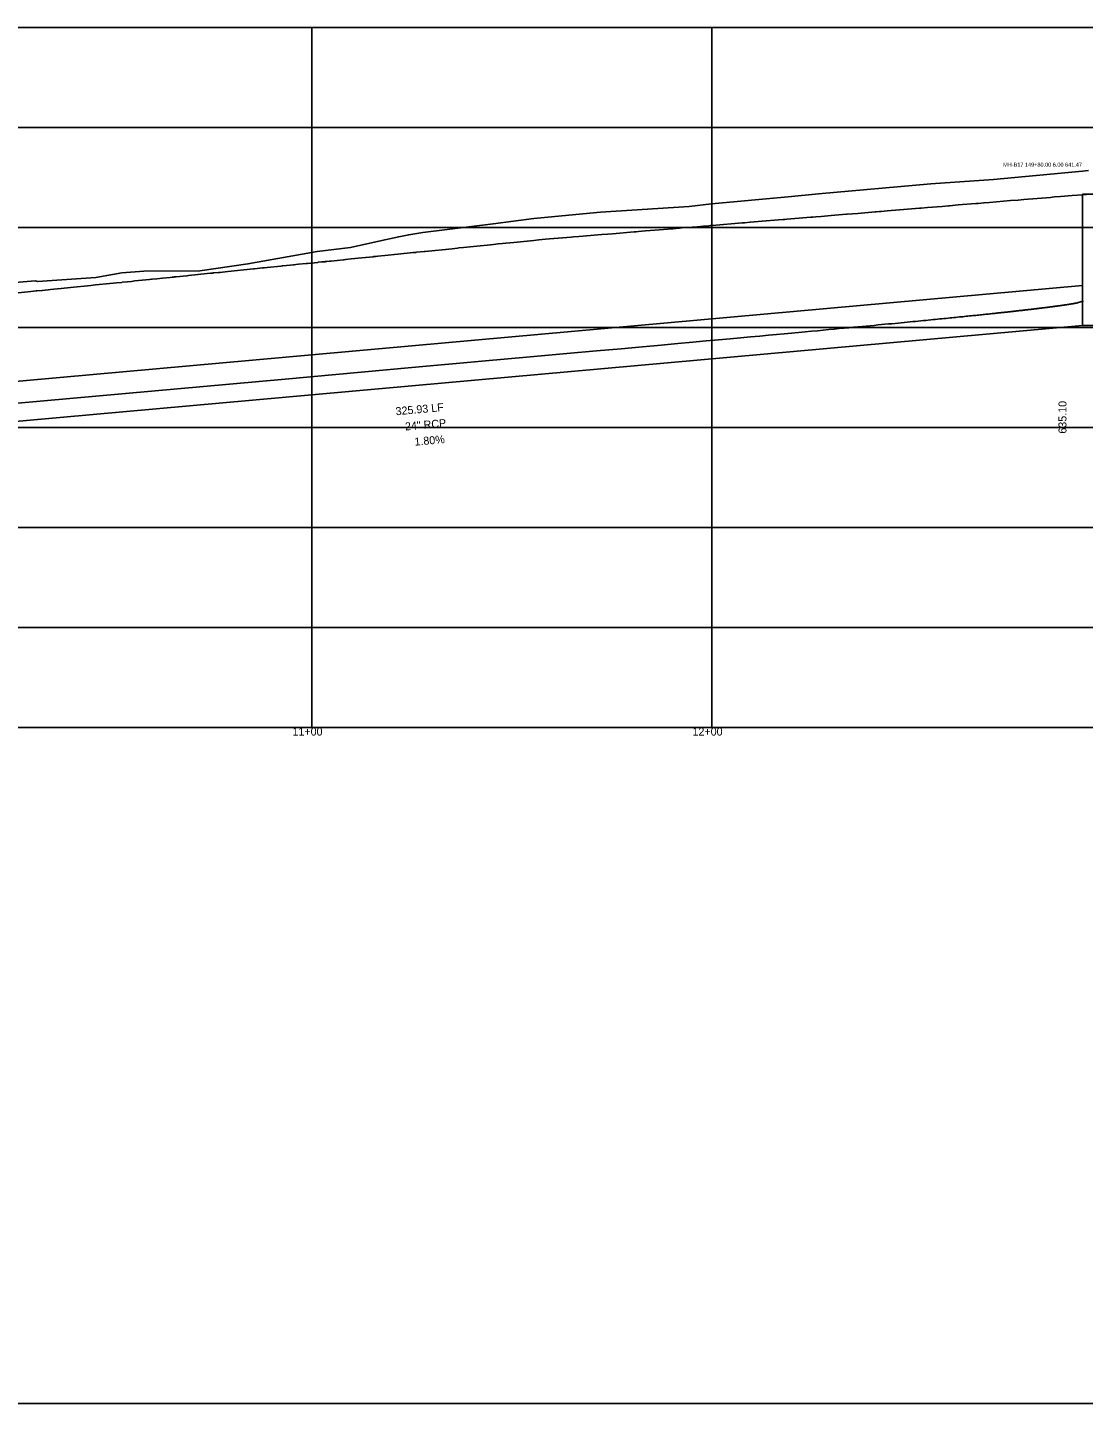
# Model space of a CAD drawing. Extents: x 2253035 to 2279930, y 13774972 to 13793443.
# Drawn here: x 2260990.4 to 2261254.4, y 13791972.5 to 13792316.4 of the extents above; entities that cross this region are included whole.
import ezdxf

# ---------------------------------------------------------------- set-up
doc = ezdxf.new("R2010")
doc.units = 0
for name, color, linetype in [('Default', 7, 'Continuous'), ('E_Utility_ATT_HH', 7, 'Continuous'), ('E_Utility_ATT_PR_PVC', 7, 'Continuous'), ('E_Utility_Telephone_Telephone Pedestal_TPED_Description', 7, 'Continuous'), ('E_Utillity_Water_Water Line_12in', 7, 'Continuous'), ('E_Utillity_Water_Water Line_1in', 7, 'Continuous'), ('E_Utillity_Water_Water Line_4in', 7, 'Continuous'), ('E_Utillity_Water_Water Line_8in', 7, 'Continuous')]:
    doc.layers.add(name, color=color, linetype=linetype)

msp = doc.modelspace()

# ---------------------------------------------------------------- linework, layer by layer
at = {"layer": 'Default'}
for p, q in [((2261061.48, 13792141.44), (2261061.48, 13792316.44)), ((2261161.48, 13792141.44), (2261161.48, 13792316.44)), ((2259961.48, 13792291.44), (2261350.66, 13792291.44)), ((2259961.48, 13792266.44), (2261350.66, 13792266.44)), ((2259961.48, 13792241.44), (2261350.66, 13792241.44)), ((2259961.48, 13792216.44), (2261350.66, 13792216.44)), ((2259961.48, 13792191.44), (2261350.66, 13792191.44)), ((2259961.48, 13792166.44), (2261350.66, 13792166.44)), ((2258357.4, 13791972.48), (2265626.63, 13791972.48))]:
    msp.add_line(p, q, dxfattribs=at)
msp.add_lwpolyline([(2259961.48, 13792141.44), (2259961.48, 13792316.44), (2261350.66, 13792316.44), (2261350.66, 13792141.44)], close=True, dxfattribs=at)
at = {"layer": 'E_Utility_ATT_PR_PVC'}
msp.add_lwpolyline([(2260926.73, 13792217.03), (2261054.83, 13792228.56), (2261086.54, 13792231.42), (2261104.03, 13792233), (2261116.08, 13792234.09), (2261125.26, 13792234.92), (2261132.66, 13792235.59), (2261138.86, 13792236.15), (2261144.18, 13792236.64), (2261148.84, 13792237.06), (2261152.99, 13792237.44), (2261156.72, 13792237.78), (2261160.11, 13792238.09), (2261163.21, 13792238.37), (2261166.06, 13792238.64), (2261168.71, 13792238.88), (2261171.17, 13792239.11), (2261173.48, 13792239.32), (2261175.65, 13792239.52), (2261177.69, 13792239.71), (2261179.62, 13792239.89), (2261181.44, 13792240.06), (2261183.18, 13792240.22), (2261184.83, 13792240.37), (2261186.41, 13792240.52), (2261187.91, 13792240.66), (2261189.35, 13792240.79), (2261190.73, 13792240.92), (2261192.06, 13792241.05), (2261193.34, 13792241.17), (2261194.56, 13792241.28), (2261195.75, 13792241.39), (2261196.89, 13792241.5), (2261197.99, 13792241.6), (2261199.06, 13792241.71), (2261200.09, 13792241.8), (2261201.09, 13792241.9), (2261202.05, 13792241.99), (2261202.99, 13792242.08), (2261203.9, 13792242.17), (2261204.79, 13792242.25), (2261205.65, 13792242.33), (2261206.49, 13792242.41), (2261207.3, 13792242.49), (2261208.09, 13792242.57), (2261208.86, 13792242.64), (2261209.61, 13792242.72), (2261210.35, 13792242.79), (2261211.06, 13792242.86), (2261211.76, 13792242.92), (2261212.44, 13792242.99), (2261213.11, 13792243.05), (2261213.76, 13792243.12), (2261214.39, 13792243.18), (2261215.01, 13792243.24), (2261215.62, 13792243.3), (2261216.22, 13792243.36), (2261216.8, 13792243.42), (2261217.37, 13792243.47), (2261217.92, 13792243.53), (2261218.47, 13792243.58), (2261219.01, 13792243.64), (2261219.53, 13792243.69), (2261220.05, 13792243.74), (2261220.55, 13792243.79), (2261221.05, 13792243.84), (2261221.53, 13792243.89), (2261222.01, 13792243.94), (2261222.48, 13792243.98), (2261222.94, 13792244.03), (2261223.39, 13792244.08), (2261223.83, 13792244.12), (2261224.26, 13792244.16), (2261224.69, 13792244.21), (2261225.11, 13792244.25), (2261225.53, 13792244.29), (2261225.93, 13792244.33), (2261226.33, 13792244.37), (2261226.72, 13792244.42), (2261227.11, 13792244.45), (2261227.49, 13792244.49), (2261227.86, 13792244.53), (2261228.23, 13792244.57), (2261228.59, 13792244.61), (2261228.95, 13792244.65), (2261229.3, 13792244.68), (2261229.64, 13792244.72), (2261229.98, 13792244.75), (2261230.32, 13792244.79), (2261230.64, 13792244.82), (2261230.97, 13792244.86), (2261231.29, 13792244.89), (2261231.6, 13792244.92), (2261231.91, 13792244.96), (2261232.22, 13792244.99), (2261232.52, 13792245.02), (2261232.82, 13792245.05), (2261233.11, 13792245.09), (2261233.4, 13792245.12), (2261233.68, 13792245.15), (2261233.96, 13792245.18), (2261234.24, 13792245.21), (2261234.51, 13792245.24), (2261234.78, 13792245.27), (2261235.05, 13792245.29), (2261235.31, 13792245.32), (2261235.57, 13792245.35), (2261235.82, 13792245.38), (2261236.07, 13792245.41), (2261236.32, 13792245.43), (2261236.56, 13792245.46), (2261236.8, 13792245.49), (2261237.04, 13792245.51), (2261237.28, 13792245.54), (2261237.51, 13792245.57), (2261237.74, 13792245.59), (2261237.96, 13792245.62), (2261238.19, 13792245.64), (2261238.41, 13792245.67), (2261238.62, 13792245.69), (2261238.84, 13792245.72), (2261239.05, 13792245.74), (2261239.26, 13792245.76), (2261239.47, 13792245.79), (2261239.67, 13792245.81), (2261239.87, 13792245.83), (2261240.07, 13792245.86), (2261240.27, 13792245.88), (2261240.46, 13792245.9), (2261240.66, 13792245.92), (2261240.84, 13792245.95), (2261241.03, 13792245.97), (2261241.22, 13792245.99), (2261241.4, 13792246.01), (2261241.58, 13792246.03), (2261241.76, 13792246.05), (2261241.94, 13792246.07), (2261242.11, 13792246.1), (2261242.28, 13792246.12), (2261242.45, 13792246.14), (2261242.62, 13792246.16), (2261242.79, 13792246.18), (2261242.95, 13792246.2), (2261243.11, 13792246.22), (2261243.27, 13792246.23), (2261243.43, 13792246.25), (2261243.59, 13792246.27), (2261243.74, 13792246.29), (2261243.9, 13792246.31), (2261244.05, 13792246.33), (2261244.2, 13792246.35), (2261244.35, 13792246.37), (2261244.49, 13792246.38), (2261244.64, 13792246.4), (2261244.78, 13792246.42), (2261244.92, 13792246.44), (2261245.06, 13792246.46), (2261245.2, 13792246.47), (2261245.33, 13792246.49), (2261245.47, 13792246.51), (2261245.6, 13792246.52), (2261245.73, 13792246.54), (2261245.87, 13792246.56), (2261245.99, 13792246.57), (2261246.12, 13792246.59), (2261246.25, 13792246.61), (2261246.37, 13792246.62), (2261246.5, 13792246.64), (2261246.62, 13792246.66), (2261246.74, 13792246.67), (2261246.86, 13792246.69), (2261246.98, 13792246.7), (2261247.09, 13792246.72), (2261247.21, 13792246.73), (2261247.32, 13792246.75), (2261247.44, 13792246.76), (2261247.55, 13792246.78), (2261247.66, 13792246.79), (2261247.77, 13792246.81), (2261247.87, 13792246.82), (2261247.98, 13792246.84), (2261248.09, 13792246.85), (2261248.19, 13792246.87), (2261248.29, 13792246.88), (2261248.4, 13792246.9), (2261248.5, 13792246.91), (2261248.6, 13792246.92), (2261248.7, 13792246.94), (2261248.79, 13792246.95), (2261248.89, 13792246.97), (2261248.99, 13792246.98), (2261249.08, 13792246.99), (2261249.17, 13792247.01), (2261249.27, 13792247.02), (2261249.36, 13792247.03), (2261249.45, 13792247.05), (2261249.54, 13792247.06), (2261249.63, 13792247.07), (2261249.71, 13792247.08), (2261249.8, 13792247.1), (2261249.89, 13792247.11), (2261249.97, 13792247.12), (2261250.05, 13792247.14), (2261250.14, 13792247.15), (2261250.22, 13792247.16), (2261250.3, 13792247.17), (2261250.38, 13792247.18), (2261250.46, 13792247.2), (2261250.54, 13792247.21), (2261250.62, 13792247.22), (2261250.69, 13792247.23), (2261250.77, 13792247.24), (2261250.84, 13792247.26), (2261250.92, 13792247.27), (2261250.99, 13792247.28), (2261251.06, 13792247.29), (2261251.13, 13792247.3), (2261251.2, 13792247.31), (2261251.27, 13792247.32), (2261251.34, 13792247.34), (2261251.41, 13792247.35), (2261251.48, 13792247.36), (2261251.55, 13792247.37), (2261251.61, 13792247.38), (2261251.68, 13792247.39), (2261251.74, 13792247.4), (2261251.81, 13792247.41), (2261251.87, 13792247.42), (2261251.93, 13792247.43), (2261251.99, 13792247.44), (2261252.05, 13792247.46), (2261252.11, 13792247.47), (2261252.17, 13792247.48), (2261252.23, 13792247.49), (2261252.29, 13792247.5), (2261252.35, 13792247.51), (2261252.41, 13792247.52), (2261252.46, 13792247.53), (2261252.52, 13792247.54), (2261252.57, 13792247.55), (2261252.63, 13792247.56), (2261252.68, 13792247.57), (2261252.73, 13792247.58), (2261252.78, 13792247.6), (2261252.84, 13792247.61), (2261252.89, 13792247.63), (2261252.94, 13792247.64), (2261252.99, 13792247.65), (2261253.04, 13792247.67), (2261253.09, 13792247.68), (2261253.13, 13792247.69), (2261253.18, 13792247.71), (2261253.23, 13792247.72), (2261253.27, 13792247.73), (2261253.32, 13792247.75), (2261253.36, 13792247.76), (2261253.41, 13792247.77), (2261253.45, 13792247.79), (2261253.5, 13792247.8), (2261253.54, 13792247.81), (2261253.58, 13792247.83), (2261253.62, 13792247.84), (2261253.66, 13792247.85), (2261253.71, 13792247.86), (2261253.75, 13792247.87), (2261253.79, 13792247.89), (2261253.82, 13792247.9), (2261253.86, 13792247.91), (2261253.9, 13792247.92), (2261253.94, 13792247.93), (2261253.98, 13792247.95), (2261254.01, 13792247.96), (2261254.05, 13792247.97), (2261254.08, 13792247.98), (2261254.12, 13792247.99), (2261254.15, 13792248), (2261254.19, 13792248.01), (2261254.22, 13792248.03), (2261254.25, 13792248.04), (2261254.29, 13792248.05), (2261254.32, 13792248.06), (2261254.35, 13792248.07), (2261254.38, 13792248.08), (2261254.41, 13792248.09), (2261254.44, 13792248.1)], dxfattribs=at)
at = {"layer": 'E_Utillity_Water_Water Line_12in'}
msp.add_lwpolyline([(2261254.16, 13792274.78), (2261257.16, 13792274.78), (2261257.16, 13792241.94), (2261254.16, 13792241.94)], close=True, dxfattribs=at)
at = {"layer": 'E_Utillity_Water_Water Line_1in'}
msp.add_lwpolyline([(2260987.35, 13792252.7), (2260992.38, 13792253.09), (2260992.96, 13792252.94), (2261007.51, 13792253.92), (2261014.05, 13792255.16), (2261019.51, 13792255.52), (2261033.51, 13792255.61), (2261045.54, 13792257.33), (2261062.82, 13792260.44), (2261071.18, 13792261.43), (2261079.76, 13792263.38), (2261083.24, 13792264.12), (2261085.76, 13792264.64), (2261089.25, 13792265.17), (2261106.87, 13792267.4), (2261117.02, 13792268.7), (2261133.7, 13792270.32), (2261155.85, 13792271.7), (2261161.43, 13792272.38), (2261180.58, 13792274.08), (2261188.14, 13792274.9), (2261216.28, 13792277.35), (2261231.93, 13792278.48), (2261254.16, 13792280.53), (2261254.16, 13792280.53), (2261255.66, 13792280.67)], dxfattribs=at)
at = {"layer": 'E_Utillity_Water_Water Line_4in'}
for p, q in [((2260928.23, 13792222.61), (2261254.16, 13792251.94)), ((2260928.23, 13792212.61), (2261254.16, 13792241.94))]:
    msp.add_line(p, q, dxfattribs=at)
at = {"layer": 'E_Utillity_Water_Water Line_8in'}
msp.add_lwpolyline([(2260988.13, 13792250.12), (2260991.31, 13792250.44), (2260992.63, 13792250.59), (2260992.69, 13792250.59), (2260992.74, 13792250.59), (2260994.12, 13792250.73), (2260995.64, 13792250.88), (2260996.16, 13792250.93), (2260997.06, 13792251.03), (2260998.86, 13792251.21), (2261001.17, 13792251.44), (2261006.29, 13792251.96), (2261007.46, 13792252.08), (2261011.04, 13792252.44), (2261012.68, 13792252.61), (2261012.69, 13792252.61), (2261012.71, 13792252.61), (2261014, 13792252.74), (2261014.08, 13792252.75), (2261015.47, 13792252.89), (2261016.43, 13792252.99), (2261017.3, 13792253.08), (2261020.9, 13792253.44), (2261021.43, 13792253.5), (2261021.43, 13792253.5), (2261021.55, 13792253.51), (2261021.56, 13792253.51), (2261021.59, 13792253.51), (2261021.59, 13792253.51), (2261021.62, 13792253.52), (2261022.78, 13792253.63), (2261024.16, 13792253.77), (2261026.12, 13792253.97), (2261026.57, 13792254.02), (2261026.92, 13792254.06), (2261027.17, 13792254.08), (2261027.55, 13792254.12), (2261027.58, 13792254.12), (2261027.6, 13792254.13), (2261027.6, 13792254.13), (2261030.27, 13792254.4), (2261030.35, 13792254.41), (2261030.38, 13792254.41), (2261030.39, 13792254.41), (2261030.39, 13792254.41), (2261030.7, 13792254.44), (2261035.36, 13792254.92), (2261036.15, 13792255), (2261036.74, 13792255.06), (2261036.97, 13792255.08), (2261038.22, 13792255.21), (2261038.56, 13792255.24), (2261039.2, 13792255.31), (2261040.51, 13792255.44), (2261046.93, 13792256.1), (2261047.21, 13792256.13), (2261049.21, 13792256.33), (2261049.56, 13792256.37), (2261050.32, 13792256.44), (2261053.75, 13792256.79), (2261054.13, 13792256.83), (2261054.27, 13792256.85), (2261056.11, 13792257.03), (2261056.9, 13792257.11), (2261057.06, 13792257.13), (2261057.13, 13792257.14), (2261057.53, 13792257.18), (2261058.22, 13792257.25), (2261060.14, 13792257.44), (2261060.36, 13792257.49), (2261060.37, 13792257.49), (2261060.37, 13792257.47), (2261060.39, 13792257.47), (2261060.39, 13792257.47), (2261060.39, 13792257.47), (2261060.4, 13792257.47), (2261060.4, 13792257.47), (2261063.03, 13792257.74), (2261063.13, 13792257.75), (2261064.04, 13792257.84), (2261064.75, 13792257.91), (2261064.93, 13792257.93), (2261065.11, 13792257.95), (2261065.21, 13792257.96), (2261065.24, 13792257.96), (2261065.29, 13792257.97), (2261065.3, 13792257.97), (2261065.97, 13792258.04), (2261066.27, 13792258.07), (2261069.41, 13792258.39), (2261069.58, 13792258.41), (2261069.95, 13792258.44), (2261071.33, 13792258.58), (2261073.99, 13792258.85), (2261076.82, 13792259.14), (2261077.04, 13792259.17), (2261077.18, 13792259.18), (2261077.47, 13792259.21), (2261077.51, 13792259.21), (2261077.98, 13792259.26), (2261079.77, 13792259.44), (2261083.02, 13792259.77), (2261086.87, 13792260.17), (2261087.61, 13792260.24), (2261087.71, 13792260.25), (2261089.58, 13792260.44), (2261089.65, 13792260.45), (2261089.84, 13792260.47), (2261096.57, 13792261.16), (2261097.9, 13792261.29), (2261098.3, 13792261.33), (2261099.39, 13792261.44), (2261102.77, 13792261.79), (2261106.17, 13792262.13), (2261106.91, 13792262.21), (2261108.1, 13792262.33), (2261109.21, 13792262.44), (2261109.98, 13792262.52), (2261112.05, 13792262.73), (2261117.03, 13792263.24), (2261118.29, 13792263.37), (2261119.1, 13792263.44), (2261119.94, 13792263.51), (2261120.96, 13792263.6), (2261126.31, 13792264.04), (2261126.9, 13792264.09), (2261128.22, 13792264.2), (2261131.15, 13792264.44), (2261132.97, 13792264.59), (2261134.03, 13792264.68), (2261135.45, 13792264.8), (2261136.71, 13792264.91), (2261142.07, 13792265.35), (2261142.59, 13792265.39), (2261143.19, 13792265.44), (2261144, 13792265.51), (2261144.89, 13792265.58), (2261147.29, 13792265.78), (2261150.47, 13792266.05), (2261150.91, 13792266.08), (2261151.76, 13792266.15), (2261152.55, 13792266.22), (2261153.41, 13792266.29), (2261154, 13792266.34), (2261155.23, 13792266.44), (2261157.83, 13792266.66), (2261159.42, 13792266.79), (2261159.78, 13792266.82), (2261160.76, 13792266.9), (2261161.1, 13792266.93), (2261161.59, 13792266.97), (2261163.51, 13792267.13), (2261167.28, 13792267.44), (2261169.1, 13792267.59), (2261169.65, 13792267.64), (2261171.05, 13792267.76), (2261175.11, 13792268.09), (2261177.17, 13792268.27), (2261178.2, 13792268.35), (2261179.32, 13792268.44), (2261179.72, 13792268.48), (2261180.23, 13792268.52), (2261186.24, 13792269.02), (2261186.75, 13792269.06), (2261187.5, 13792269.12), (2261188.8, 13792269.23), (2261191.36, 13792269.44), (2261194.16, 13792269.68), (2261195.14, 13792269.76), (2261195.3, 13792269.77), (2261197.97, 13792269.99), (2261202.36, 13792270.36), (2261202.56, 13792270.37), (2261203.4, 13792270.44), (2261203.8, 13792270.48), (2261203.85, 13792270.48), (2261203.85, 13792270.48), (2261205.33, 13792270.6), (2261208.42, 13792270.86), (2261212.4, 13792271.19), (2261213.46, 13792271.28), (2261213.87, 13792271.31), (2261215.45, 13792271.44), (2261219.08, 13792271.74), (2261220.67, 13792271.88), (2261220.95, 13792271.9), (2261223.07, 13792272.08), (2261227.49, 13792272.44), (2261227.94, 13792272.48), (2261228.05, 13792272.49), (2261229.5, 13792272.61), (2261229.55, 13792272.61), (2261230.95, 13792272.73), (2261236.21, 13792273.17), (2261238.05, 13792273.32), (2261239.48, 13792273.44), (2261239.49, 13792273.44), (2261239.53, 13792273.44), (2261246.17, 13792273.99), (2261246.6, 13792274.03), (2261247.21, 13792274.08), (2261248.69, 13792274.2), (2261251.58, 13792274.44), (2261254.16, 13792274.66), (2261254.16, 13792274.66), (2261254.28, 13792274.67), (2261255.14, 13792274.74)], dxfattribs=at)

# ---------------------------------------------------------------- texts
at = {"layer": 'Default'}
for s, p in [('11+00', (2261056.68, 13792139.44)), ('12+00', (2261156.68, 13792139.44))]:
    msp.add_text(s, height=2, dxfattribs=at).set_placement(p)
at = {"layer": 'E_Utility_ATT_HH'}
for s, rotation, p in [('635.10', 90, (2261250.16, 13792214.92)), ('325.93 LF', 5.1428, (2261082.55, 13792219.5)), ('24" RCP', 5.1428, (2261084.9, 13792215.7)), ('1.80%', 5.1428, (2261087.26, 13792211.89))]:
    msp.add_text(s, height=2, rotation=rotation, dxfattribs=at).set_placement(p)
at = {"layer": 'E_Utility_Telephone_Telephone Pedestal_TPED_Description'}
msp.add_text('MH-B17 149+80.00 6.00 641.47', height=1, rotation=0, dxfattribs=at).set_placement((2261234.34, 13792281.66))

doc.saveas('drawing.dxf')
